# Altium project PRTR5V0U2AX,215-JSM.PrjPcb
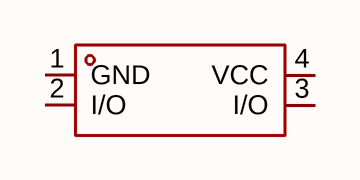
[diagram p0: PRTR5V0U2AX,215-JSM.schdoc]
1 sheet, 1 parts. Net scope: global (net labels, ports and power ports of the same name join across sheets).

## Sheet PRTR5V0U2AX,215-JSM.schdoc
size 127 x 101 mm

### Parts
D?  prtr5v0u2ax,215-jsm  [SOT-143-4_L2.9-W1.3-P1.92-LS2.3-BL]  (value not drawn)

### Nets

Not connected (* = marked no-connect by the designer): D? 1(GND) 2(I/O) 3(I/O) 4(VCC)

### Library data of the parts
D? = prtr5v0u2ax,215-jsm: 极性:-;反向截止电压(Vrwm):5V;钳位电压:15V；18V;峰值脉冲电流(Ipp):4A@8/20us；3A@8/20us;峰值脉冲功率(Ppp):60W@8/20us；45W@8/20us;击穿电压(VBR):7.5V;; Manufacturer: JSMSEMI(杰盛微); AddInBom: yes; ModelId: 7d12f14c739449dbb8dc40b2fe6e071f; ModelName: SOT-143_L2.9-W1.3-H1.0-LS2.4-P1.92; ModelTransform: 114.173,94.488,0,0,0,0,0,0.005,0; Reverse Stand-Off Voltage (Vrwm): 5V; Voltage - Breakdown: 7.5V; Reverse Leakage Current (Ir): 500nA; Number of Channels: 双路; level of protection: IEC 61000-4-2; Type: ESD; Junction Capacitance: 0.7pF；0.4pF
